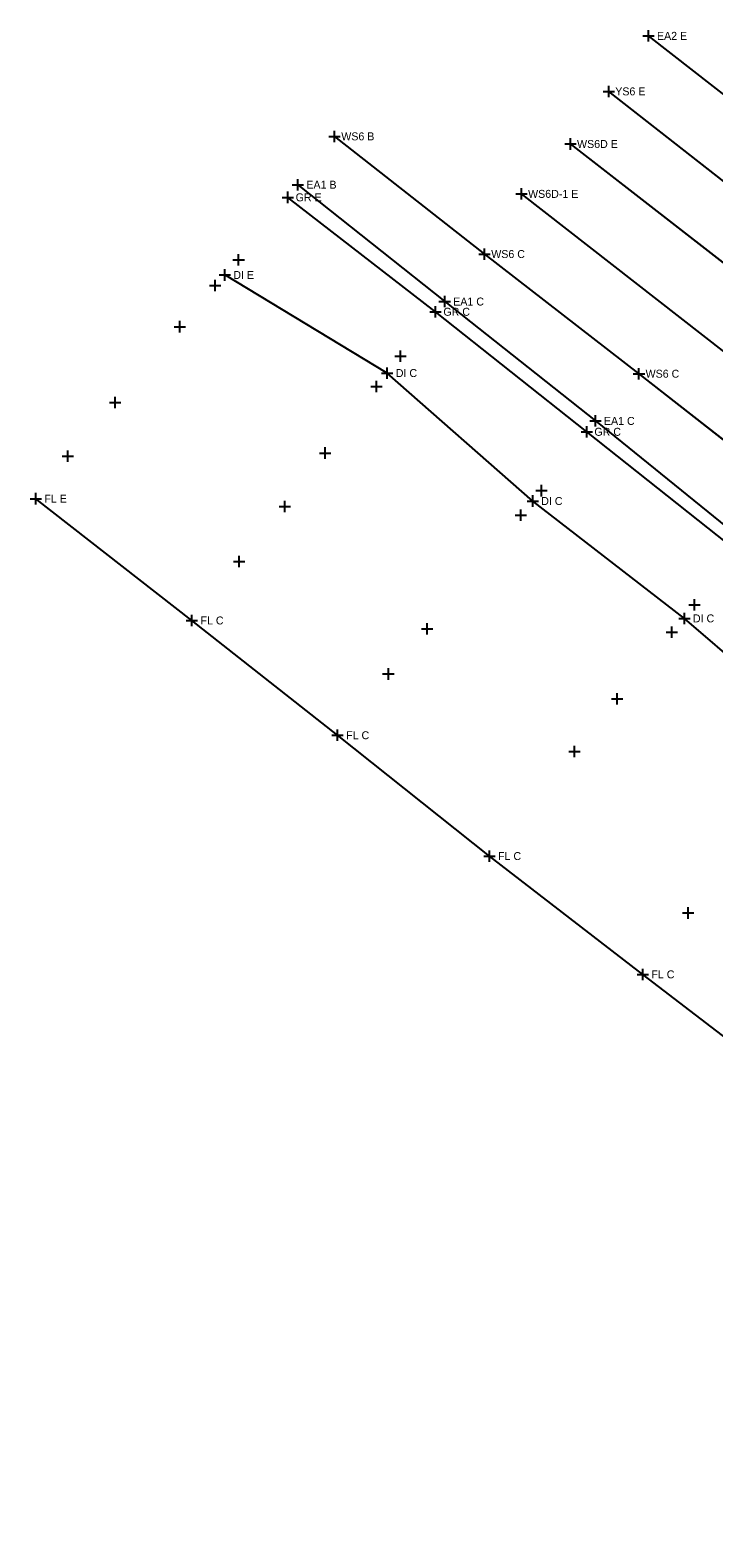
# Model space of a CAD drawing. Extents: x 1324236 to 1326110, y 459090 to 460782.
# Drawn here: x 1324236 to 1324356.3, y 460378.3 to 460643.4 of the extents above; entities that cross this region are included whole.
import ezdxf

# ---------------------------------------------------------------- set-up
doc = ezdxf.new("R2010")
doc.units = 0
for name, color, linetype in [('BD_X_Canopy', 7, 'Continuous'), ('DR_X_Ditch', 7, 'Continuous'), ('DR_X_Drive_Pipe', 7, 'Continuous'), ('DV_X_Property_Line', 7, 'Continuous'), ('PM_X_CL_Double_Solid', 7, 'Continuous'), ('PM_X_Edge_Line', 7, 'Continuous'), ('PM_X_Lane_Line', 7, 'Continuous'), ('PM_X_Parking_Lot_Stall', 7, 'Continuous'), ('PV_X_Shoulder', 7, 'Continuous'), ('RW_X_CL', 7, 'Continuous'), ('RW_X_Esmt_SH', 7, 'Continuous')]:
    doc.layers.add(name, color=color, linetype=linetype)

msp = doc.modelspace()

# ---------------------------------------------------------------- linework, layer by layer
at = {"layer": 'BD_X_Canopy'}
msp.add_lwpolyline([(1324658.11, 460368.1), (1324570.73, 460436.38), (1324490.36, 460498.76), (1324409.95, 460562.12), (1324331.06, 460623.37)], dxfattribs=at)
at = {"layer": 'DR_X_Ditch'}
for points in [[(1324662.39, 460379.05), (1324578.69, 460444.65), (1324497.47, 460507.91), (1324417.96, 460569.9), (1324337.82, 460632.62)], [(1324289.59, 460624.7), (1324315.98, 460604.02), (1324343.13, 460582.98), (1324370.15, 460561.82)]]:
    msp.add_lwpolyline(points, dxfattribs=at)
at = {"layer": 'DR_X_Drive_Pipe'}
for p, q in [((1324298.85, 460583.1), (1324270.27, 460600.34)), ((1324324.43, 460560.6), (1324298.85, 460583.1)), ((1324351.12, 460539.96), (1324324.43, 460560.6)), ((1324376.18, 460518.42), (1324351.12, 460539.96))]:
    msp.add_line(p, q, dxfattribs=at)
at = {"layer": 'DV_X_Property_Line'}
for p, q in [((1324343.79, 460642.38), (1324345.79, 460642.38)), ((1324344.79, 460641.38), (1324344.79, 460643.38)), ((1324282.12, 460616.2), (1324284.12, 460616.2)), ((1324283.12, 460615.2), (1324283.12, 460617.2)), ((1324307.95, 460595.67), (1324309.95, 460595.67)), ((1324308.95, 460594.67), (1324308.95, 460596.67)), ((1324334.46, 460574.68), (1324336.46, 460574.68)), ((1324335.46, 460573.68), (1324335.46, 460575.68))]:
    msp.add_line(p, q, dxfattribs=at)
at = {"layer": 'PM_X_CL_Double_Solid'}
for p, q in [((1324264.5, 460539.6), (1324237.03, 460561.01)), ((1324290.12, 460519.42), (1324264.5, 460539.6)), ((1324316.84, 460498.18), (1324290.12, 460519.42)), ((1324343.81, 460477.38), (1324316.84, 460498.18)), ((1324369.58, 460457.55), (1324343.81, 460477.38))]:
    msp.add_line(p, q, dxfattribs=at)
at = {"layer": 'PM_X_Edge_Line'}
for p, q in [((1324417.96, 460569.9), (1324337.82, 460632.62)), ((1324289.59, 460624.7), (1324315.98, 460604.02)), ((1324315.98, 460604.02), (1324343.13, 460582.98)), ((1324343.13, 460582.98), (1324370.15, 460561.82))]:
    msp.add_line(p, q, dxfattribs=at)
at = {"layer": 'PM_X_Lane_Line'}
for p, q in [((1324409.95, 460562.12), (1324331.06, 460623.37)), ((1324401.75, 460552.78), (1324322.45, 460614.6))]:
    msp.add_line(p, q, dxfattribs=at)
at = {"layer": 'PM_X_Parking_Lot_Stall'}
for p, q in [((1324307.36, 460593.87), (1324281.38, 460613.99)), ((1324333.93, 460572.77), (1324307.36, 460593.87)), ((1324360.66, 460551.6), (1324333.93, 460572.77))]:
    msp.add_line(p, q, dxfattribs=at)
at = {"layer": 'PV_X_Shoulder'}
for points in [[(1324669.98, 460389.31), (1324586.32, 460454.48), (1324504.97, 460517.77), (1324425.87, 460579.19), (1324344.79, 460642.38)], [(1324283.12, 460616.2), (1324308.95, 460595.67), (1324335.46, 460574.68), (1324362.04, 460553.18)]]:
    msp.add_lwpolyline(points, dxfattribs=at)
at = {"layer": 'RW_X_CL'}
for p, q in [((1324336.82, 460632.62), (1324338.82, 460632.62)), ((1324337.82, 460631.62), (1324337.82, 460633.62)), ((1324288.59, 460624.7), (1324290.59, 460624.7)), ((1324289.59, 460623.7), (1324289.59, 460625.7)), ((1324331.06, 460622.37), (1324331.06, 460624.37)), ((1324330.06, 460623.37), (1324332.06, 460623.37)), ((1324321.45, 460614.6), (1324323.45, 460614.6)), ((1324322.45, 460613.6), (1324322.45, 460615.6)), ((1324315.98, 460603.02), (1324315.98, 460605.02)), ((1324271.71, 460603), (1324273.71, 460603)), ((1324272.71, 460602), (1324272.71, 460604)), ((1324314.98, 460604.02), (1324316.98, 460604.02)), ((1324267.58, 460598.47), (1324269.58, 460598.47)), ((1324268.58, 460597.47), (1324268.58, 460599.47)), ((1324262.34, 460590.25), (1324262.34, 460592.25)), ((1324261.34, 460591.25), (1324263.34, 460591.25)), ((1324301.18, 460585.07), (1324301.18, 460587.07)), ((1324300.18, 460586.07), (1324302.18, 460586.07)), ((1324343.13, 460581.98), (1324343.13, 460583.98)), ((1324296.95, 460579.73), (1324296.95, 460581.73)), ((1324342.13, 460582.98), (1324344.13, 460582.98)), ((1324251.01, 460576.93), (1324251.01, 460578.93)), ((1324295.95, 460580.73), (1324297.95, 460580.73)), ((1324250.01, 460577.93), (1324252.01, 460577.93)), ((1324241.67, 460568.49), (1324243.67, 460568.49)), ((1324242.67, 460567.49), (1324242.67, 460569.49)), ((1324286.94, 460569.04), (1324288.94, 460569.04)), ((1324287.94, 460568.04), (1324287.94, 460570.04)), ((1324325.97, 460561.42), (1324325.97, 460563.42)), ((1324280.82, 460558.66), (1324280.82, 460560.66)), ((1324324.97, 460562.42), (1324326.97, 460562.42)), ((1324279.82, 460559.66), (1324281.82, 460559.66)), ((1324321.36, 460558.1), (1324323.36, 460558.1)), ((1324322.36, 460557.1), (1324322.36, 460559.1)), ((1324271.78, 460549.97), (1324273.78, 460549.97)), ((1324272.78, 460548.97), (1324272.78, 460550.97)), ((1324351.9, 460542.35), (1324353.9, 460542.35)), ((1324352.9, 460541.35), (1324352.9, 460543.35)), ((1324305.85, 460537.11), (1324305.85, 460539.11)), ((1324304.85, 460538.11), (1324306.85, 460538.11)), ((1324347.93, 460537.53), (1324349.93, 460537.53)), ((1324348.93, 460536.53), (1324348.93, 460538.53)), ((1324299.04, 460529.19), (1324299.04, 460531.19)), ((1324298.04, 460530.19), (1324300.04, 460530.19)), ((1324338.31, 460525.84), (1324340.31, 460525.84)), ((1324339.31, 460524.84), (1324339.31, 460526.84)), ((1324331.76, 460515.54), (1324331.76, 460517.54)), ((1324330.76, 460516.54), (1324332.76, 460516.54)), ((1324351.78, 460487.17), (1324351.78, 460489.17)), ((1324350.78, 460488.17), (1324352.78, 460488.17))]:
    msp.add_line(p, q, dxfattribs=at)
at = {"layer": 'RW_X_Esmt_SH'}
for p, q in [((1324280.38, 460613.99), (1324282.38, 460613.99)), ((1324281.38, 460612.99), (1324281.38, 460614.99)), ((1324269.27, 460600.34), (1324271.27, 460600.34)), ((1324270.27, 460599.34), (1324270.27, 460601.34)), ((1324307.36, 460592.87), (1324307.36, 460594.87)), ((1324306.36, 460593.87), (1324308.36, 460593.87)), ((1324298.85, 460582.1), (1324298.85, 460584.1)), ((1324297.85, 460583.1), (1324299.85, 460583.1)), ((1324333.93, 460571.76), (1324333.93, 460573.76)), ((1324332.93, 460572.77), (1324334.93, 460572.77)), ((1324236.03, 460561.01), (1324238.03, 460561.01)), ((1324237.03, 460560.01), (1324237.03, 460562.01)), ((1324323.43, 460560.6), (1324325.43, 460560.6)), ((1324324.43, 460559.6), (1324324.43, 460561.6)), ((1324263.5, 460539.6), (1324265.5, 460539.6)), ((1324264.5, 460538.6), (1324264.5, 460540.6)), ((1324350.12, 460539.96), (1324352.12, 460539.96)), ((1324351.12, 460538.96), (1324351.12, 460540.96)), ((1324290.12, 460518.42), (1324290.12, 460520.42)), ((1324289.12, 460519.42), (1324291.12, 460519.42)), ((1324316.84, 460497.18), (1324316.84, 460499.18)), ((1324315.84, 460498.18), (1324317.84, 460498.18)), ((1324343.81, 460476.38), (1324343.81, 460478.38)), ((1324342.81, 460477.38), (1324344.81, 460477.38))]:
    msp.add_line(p, q, dxfattribs=at)

# ---------------------------------------------------------------- texts
at = {"layer": 'DV_X_Property_Line'}
for s, p in [('EA2 E', (1324346.29, 460641.68)), ('EA1 B', (1324284.62, 460615.51)), ('EA1 C', (1324310.45, 460594.97)), ('EA1 C', (1324336.96, 460573.98))]:
    msp.add_text(s, height=1.4, dxfattribs=at).set_placement(p)
at = {"layer": 'RW_X_CL'}
for s, p in [('YS6 E', (1324338.95, 460631.92)), ('WS6 B', (1324290.76, 460624.01)), ('WS6D E', (1324332.23, 460622.67)), ('WS6D-1 E', (1324323.62, 460613.9)), ('WS6 C', (1324317.14, 460603.32)), ('WS6 C', (1324344.29, 460582.28))]:
    msp.add_text(s, height=1.4, dxfattribs=at).set_placement(p)
at = {"layer": 'RW_X_Esmt_SH'}
for s, p in [('GR E', (1324282.74, 460613.29)), ('DI E', (1324271.77, 460599.64)), ('GR C', (1324308.72, 460593.17)), ('DI C', (1324300.35, 460582.4)), ('GR C', (1324335.28, 460572.07)), ('FL E', (1324238.53, 460560.31)), ('DI C', (1324325.93, 460559.9)), ('FL C', (1324266, 460538.9)), ('DI C', (1324352.62, 460539.26)), ('FL C', (1324291.62, 460518.72)), ('FL C', (1324318.34, 460497.48)), ('FL C', (1324345.31, 460476.68))]:
    msp.add_text(s, height=1.4, dxfattribs=at).set_placement(p)

doc.saveas('drawing.dxf')
